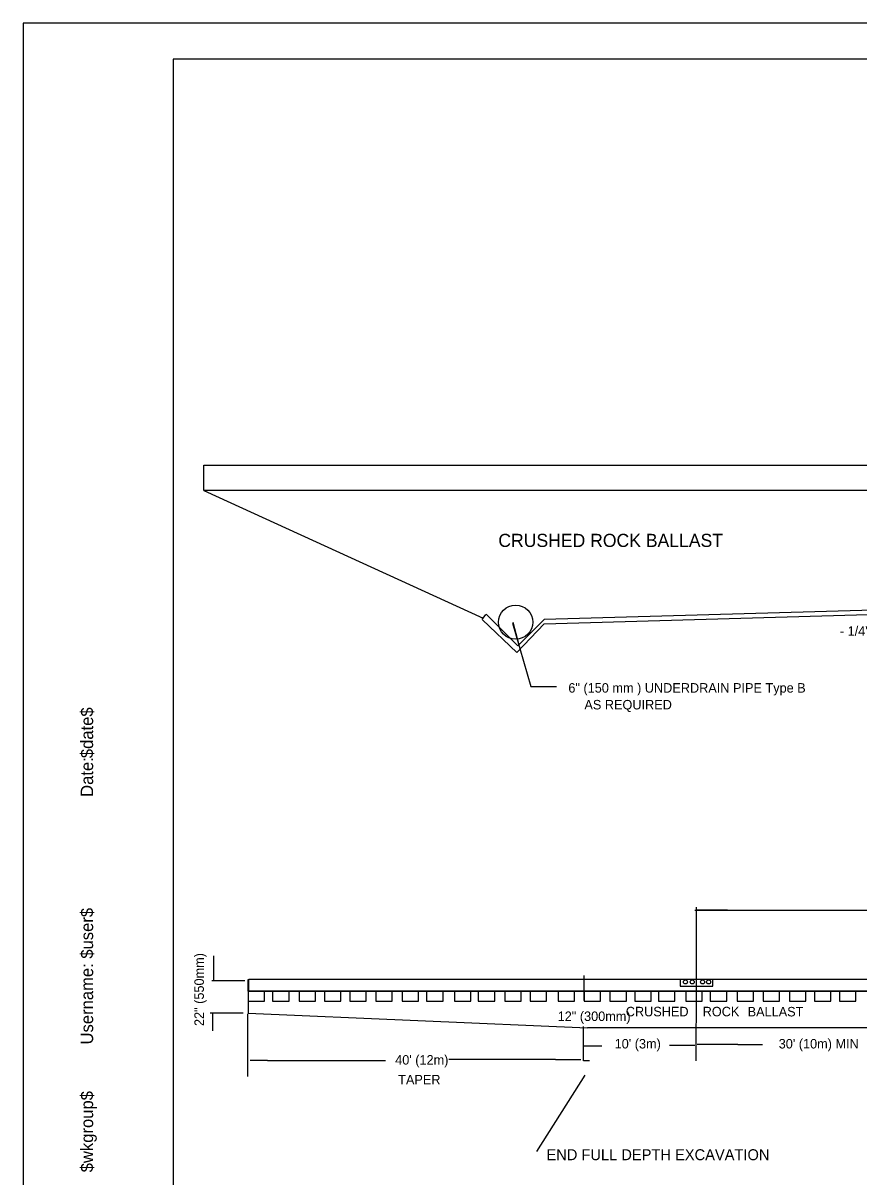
# Model space of a CAD drawing. Extents: x 1100953.69 to 1100956.55, y 386728.28 to 386730.11.
# Drawn here: x 1100953.692 to 1100954.443, y 386729.073 to 386730.11 of the extents above; entities that cross this region are included whole.
import ezdxf

# ---------------------------------------------------------------- set-up
doc = ezdxf.new("R2010")
doc.units = 0
for name, color, linetype in [('BORDER', 7, 'Continuous'), ('Level 1', 7, 'Continuous'), ('Level 33', 7, 'Continuous'), ('ORIG TOPO TEXT', 7, 'Continuous'), ('PLOT BOUNDARY', 7, 'Continuous')]:
    doc.layers.add(name, color=color, linetype=linetype)

msp = doc.modelspace()

# ---------------------------------------------------------------- linework, layer by layer
at = {"layer": 'BORDER'}
for p, q in [((1100956.4931, 386730.0776), (1100953.8264, 386730.0776)), ((1100953.8264, 386730.0776), (1100953.8264, 386728.3276))]:
    msp.add_line(p, q, dxfattribs=at)
at = {"layer": 'Level 1'}
for p, q in [((1100953.8539, 386729.69), (1100954.1049, 386729.575)), ((1100954.2952, 386729.3127), (1100955.2955, 386729.3127)), ((1100954.2964, 386729.3153), (1100954.2964, 386729.2152)), ((1100953.8612, 386729.2494), (1100953.8907, 386729.2494)), ((1100953.8943, 386729.2506), (1100955.7055, 386729.2506)), ((1100954.2819, 386729.2506), (1100954.2819, 386729.2445)), ((1100953.8596, 386729.2204), (1100953.8892, 386729.2204)), ((1100953.8933, 386729.2196), (1100953.8933, 386729.1632)), ((1100953.8933, 386729.2196), (1100953.8933, 386729.1632)), ((1100954.1951, 386729.1773), (1100954.1951, 386729.2078)), ((1100954.1986, 386729.2071), (1100954.1986, 386729.2071)), ((1100954.2964, 386729.2152), (1100954.2959, 386729.2069)), ((1100954.3339, 386729.1921), (1100954.3558, 386729.1921)), ((1100953.9111, 386729.1777), (1100953.9053, 386729.1777)), ((1100953.9111, 386729.1777), (1100954.0172, 386729.1777)), ((1100954.1699, 386729.1785), (1100954.0742, 386729.1785)), ((1100954.2004, 386729.1773), (1100954.1951, 386729.1773))]:
    msp.add_line(p, q, dxfattribs=at)
for points in [[(1100954.4849, 386729.69), (1100953.8539, 386729.69), (1100953.8539, 386729.7126), (1100953.8539, 386729.7126), (1100954.6144, 386729.7126)], [(1100955.4278, 386729.5793), (1100955.395, 386729.5465), (1100955.3578, 386729.5763), (1100955.3578, 386729.5763), (1100954.7625, 386729.591), (1100954.1599, 386729.574), (1100954.1361, 386729.5502), (1100954.1075, 386729.5787)], [(1100954.1044, 386729.5735), (1100954.1351, 386729.5442), (1100954.1598, 386729.5701), (1100954.7626, 386729.5873), (1100955.3554, 386729.5746), (1100955.3951, 386729.5429), (1100955.4313, 386729.5776), (1100955.4313, 386729.5776), (1100955.4313, 386729.5776), (1100955.4313, 386729.5776)], [(1100955.7055, 386729.2398), (1100953.8939, 386729.2398), (1100953.8939, 386729.2503)], [(1100953.8943, 386729.2398), (1100953.8943, 386729.2506), (1100953.8943, 386729.2506), (1100955.7062, 386729.2506), (1100955.7062, 386729.2398)], [(1100954.2819, 386729.2445), (1100954.3114, 386729.2445), (1100954.3114, 386729.2505)], [(1100953.8938, 386729.2398), (1100953.8938, 386729.2308), (1100953.9086, 386729.2308), (1100953.9086, 386729.2398)], [(1100953.8943, 386729.2398), (1100953.8943, 386729.2398), (1100955.7055, 386729.2398)], [(1100953.9157, 386729.2398), (1100953.9157, 386729.2308), (1100953.9305, 386729.2308), (1100953.9305, 386729.2398)], [(1100953.9395, 386729.2398), (1100953.9395, 386729.2308), (1100953.9543, 386729.2308), (1100953.9543, 386729.2398)], [(1100953.9623, 386729.2398), (1100953.9623, 386729.2308), (1100953.9771, 386729.2308), (1100953.9771, 386729.2398)], [(1100953.9851, 386729.2398), (1100953.9851, 386729.2308), (1100953.9999, 386729.2308), (1100953.9999, 386729.2398)], [(1100954.0084, 386729.2398), (1100954.0084, 386729.2308), (1100954.0232, 386729.2308), (1100954.0232, 386729.2398)], [(1100954.0322, 386729.2398), (1100954.0322, 386729.2308), (1100954.0469, 386729.2308), (1100954.0469, 386729.2398)], [(1100954.0541, 386729.2398), (1100954.0541, 386729.2308), (1100954.0689, 386729.2308), (1100954.0689, 386729.2398)], [(1100954.0792, 386729.2398), (1100954.0792, 386729.2308), (1100954.0939, 386729.2308), (1100954.0939, 386729.2398)], [(1100954.1006, 386729.2398), (1100954.1006, 386729.2308), (1100954.1154, 386729.2308), (1100954.1154, 386729.2398)], [(1100954.1244, 386729.2398), (1100954.1244, 386729.2308), (1100954.1392, 386729.2308), (1100954.1392, 386729.2398)], [(1100954.1472, 386729.2398), (1100954.1472, 386729.2308), (1100954.162, 386729.2308), (1100954.162, 386729.2398)], [(1100954.1723, 386729.2398), (1100954.1723, 386729.2308), (1100954.1871, 386729.2308), (1100954.1871, 386729.2398)], [(1100954.1956, 386729.2398), (1100954.1956, 386729.2308), (1100954.2103, 386729.2308), (1100954.2103, 386729.2398)], [(1100954.2188, 386729.2398), (1100954.2188, 386729.2308), (1100954.2336, 386729.2308), (1100954.2336, 386729.2398)], [(1100954.2412, 386729.2398), (1100954.2412, 386729.2308), (1100954.256, 386729.2308), (1100954.256, 386729.2398)], [(1100954.2625, 386729.2398), (1100954.2625, 386729.2308), (1100954.2772, 386729.2308), (1100954.2772, 386729.2398)], [(1100954.2871, 386729.2398), (1100954.2871, 386729.2308), (1100954.3018, 386729.2308), (1100954.3018, 386729.2398)], [(1100954.309, 386729.2398), (1100954.309, 386729.2308), (1100954.3238, 386729.2308), (1100954.3238, 386729.2398)], [(1100954.3332, 386729.2398), (1100954.3332, 386729.2308), (1100954.348, 386729.2308), (1100954.348, 386729.2398)], [(1100954.3565, 386729.2398), (1100954.3565, 386729.2308), (1100954.3712, 386729.2308), (1100954.3712, 386729.2398)], [(1100954.3802, 386729.2398), (1100954.3802, 386729.2308), (1100954.395, 386729.2308), (1100954.395, 386729.2398)], [(1100954.4026, 386729.2398), (1100954.4026, 386729.2308), (1100954.4174, 386729.2308), (1100954.4174, 386729.2398)], [(1100954.425, 386729.2398), (1100954.425, 386729.2308), (1100954.4397, 386729.2308), (1100954.4397, 386729.2398)], [(1100953.8938, 386729.2308), (1100953.8938, 386729.2201), (1100954.1986, 386729.2071)], [(1100954.1987, 386729.2072), (1100955.4041, 386729.2072), (1100955.7053, 386729.2275)]]:
    msp.add_lwpolyline(points, dxfattribs=at)
for centre, radius in [((1100954.1341, 386729.5715), 0.0154), ((1100954.2867, 386729.2482), 0.00179), ((1100954.2928, 386729.2482), 0.00179), ((1100954.3021, 386729.2482), 0.00179), ((1100954.3075, 386729.2482), 0.00179)]:
    msp.add_circle(centre, radius, dxfattribs=at)
at = {"layer": 'Level 33'}
for p, q in [((1100954.1313, 386729.5705), (1100954.1477, 386729.5137)), ((1100954.1477, 386729.5137), (1100954.1707, 386729.5137)), ((1100954.2959, 386729.2069), (1100954.2959, 386729.1774))]:
    msp.add_line(p, q, dxfattribs=at)
at = {"layer": 'ORIG TOPO TEXT'}
for p, q in [((1100954.104, 386729.574), (1100954.1074, 386729.5784)), ((1100954.1373, 386729.5509), (1100954.1319, 386729.5713)), ((1100954.3245, 386729.3128), (1100954.296, 386729.3128)), ((1100953.8628, 386729.2717), (1100953.8628, 386729.2492)), ((1100954.1955, 386729.2541), (1100954.1955, 386729.2315)), ((1100953.8621, 386729.2044), (1100953.8621, 386729.22)), ((1100954.1951, 386729.1926), (1100954.1951, 386729.2082)), ((1100954.2115, 386729.1906), (1100954.1958, 386729.1906)), ((1100954.2723, 386729.1915), (1100954.2951, 386729.1915)), ((1100954.3339, 386729.1921), (1100954.2971, 386729.1921)), ((1100953.9111, 386729.1777), (1100953.8955, 386729.1777)), ((1100954.1699, 386729.1785), (1100954.1927, 386729.1785)), ((1100954.1532, 386729.0958), (1100954.1965, 386729.1643))]:
    msp.add_line(p, q, dxfattribs=at)
at = {"layer": 'PLOT BOUNDARY'}
msp.add_lwpolyline([(1100953.6916, 386728.2766), (1100956.5249, 386728.2766), (1100956.5249, 386730.1099), (1100953.6916, 386730.1099)], close=True, dxfattribs=at)

# ---------------------------------------------------------------- texts
at = {"layer": 'BORDER'}
for s, p in [('$date$', (1100953.7545, 386729.4493)), ('Date:', (1100953.7545, 386729.4145)), ('$user$', (1100953.7545, 386729.2691)), ('Username:', (1100953.7545, 386729.192)), ('$wkgroup$', (1100953.7545, 386729.0771))]:
    msp.add_text(s, height=0.01116, rotation=90, dxfattribs=at).set_placement(p)
at = {"layer": 'ORIG TOPO TEXT'}
for s, height, p in [('CRUSHED ROCK BALLAST', 0.011811, (1100954.1186, 386729.6391)), ('     - 1/4" PER FOOT SLOPE(-2 %)', 0.008531, (1100954.4096, 386729.5593)), ('6" (150 mm ) UNDERDRAIN PIPE Type B', 0.008531, (1100954.1815, 386729.5082)), ('AS REQUIRED', 0.008531, (1100954.1959, 386729.4931)), ('CRUSHED    ROCK', 0.008531, (1100954.2331, 386729.2173)), ('BALLAST', 0.00853, (1100954.3426, 386729.2172)), ('12" (300mm)', 0.008531, (1100954.1719, 386729.2131)), ("10' (3m)", 0.00853, (1100954.2231, 386729.1884)), ("30' (10m) MIN", 0.008531, (1100954.3705, 386729.1884)), ("40' (12m)", 0.00853, (1100954.0259, 386729.1739)), ('TAPER', 0.00853, (1100954.0286, 386729.1561)), ('END FULL DEPTH EXCAVATION', 0.009843, (1100954.1618, 386729.088))]:
    msp.add_text(s, height=height, dxfattribs=at).set_placement(p)
msp.add_text('22" (550mm)', height=0.008531, rotation=90, dxfattribs=at).set_placement((1100953.854, 386729.2086))

doc.saveas('drawing.dxf')
